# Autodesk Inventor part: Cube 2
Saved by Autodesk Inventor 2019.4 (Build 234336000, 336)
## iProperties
Created: 2020-12
Part Number: Cube 2
Material: Generic
Document SubType Name: Modeling
Designer: Administrator
Density: 1 g/cm^3
Appearance: Default
Title: Cube 2
Author: Administrator
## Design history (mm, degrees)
feature "Body1"
body "Solid1"
